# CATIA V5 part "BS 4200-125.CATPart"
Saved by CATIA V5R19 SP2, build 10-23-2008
Part number: BS 4200-125
Bounding box of the stored display mesh (mm): x -47.487 to 47.487, y -47.487 to 47.487, z 0 to 315
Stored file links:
  C:\Users\Bora\Desktop\3D Katı model\BS serisi\BS 4200\BS 4200-125.CATPart
  C:\Program Files\Dassault Systemes\B19\intel_a\reffiles\standard\MetricThickPitch.txt
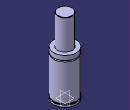
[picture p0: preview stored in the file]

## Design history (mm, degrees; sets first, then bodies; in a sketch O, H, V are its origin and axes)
Body1 (main body)
  Sketch1 on yz-plane, origin (0, 0, 0), H (0, 1, 0), V (0, 0, 1)
    point P2 (47.5, 165.5)
    point P5 (30, 314)
    point P7 (30, 314)
    point P11 (47.5, 170.5)
    point P13 (47.5, 170.5)
    point P14 (47.5, 165.5)
    line L1 (47.5, 13) -> (47.5, 165.5)
    line L2 (44.5, 13) -> (44.5, 8)
    line L3 (30, 314) -> (30, 189)
    arc A1 centre (29, 314) radius 1 from (30, 314) to (29, 315) ccw
    line L4 (47.5, 0) -> (47.5, 8)
    line L5 (47.5, 170.5) -> (47.5, 189)
    arc A2 centre (47.5, 168) radius 2.5 from (47.5, 170.5) to (47.5, 165.5) ccw
    line L6 (29, 315) -> (0, 315)
    point P15 (0, 315)
    line L7 (30, 189) -> (47.5, 189)
    line L8 (44.5, 13) -> (47.5, 13)
    line L9 (44.5, 8) -> (47.5, 8)
    line L10 (47.5, 0) -> (0, 0)
    coincidence: P15 V, P2 P14, P5 P7, P11 P13
    tangency: L6 A1
    horizontal: L7 H, L8 H, L9 H, L10 H
  Shaft1: profile Sketch1, axis Sketch1.V, angle 360
  Sketch2 on face of Shaft1 from Sketch1.L10, origin (0, 0, 0), H (1, 0, 0), V (0, -1, 0)
    point P1 (30, 0)
    distance P1 V = 30
  Hole1: placed by Sketch2, at (30, 0, 0) direction (0, 0, 1), diameter 6.647, depth 7, threaded "M8", thread diameter 8, thread depth 7, pitch 1.25
  CircPattern1: of Hole1, instances 4, angular step 90, axis from xy-plane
